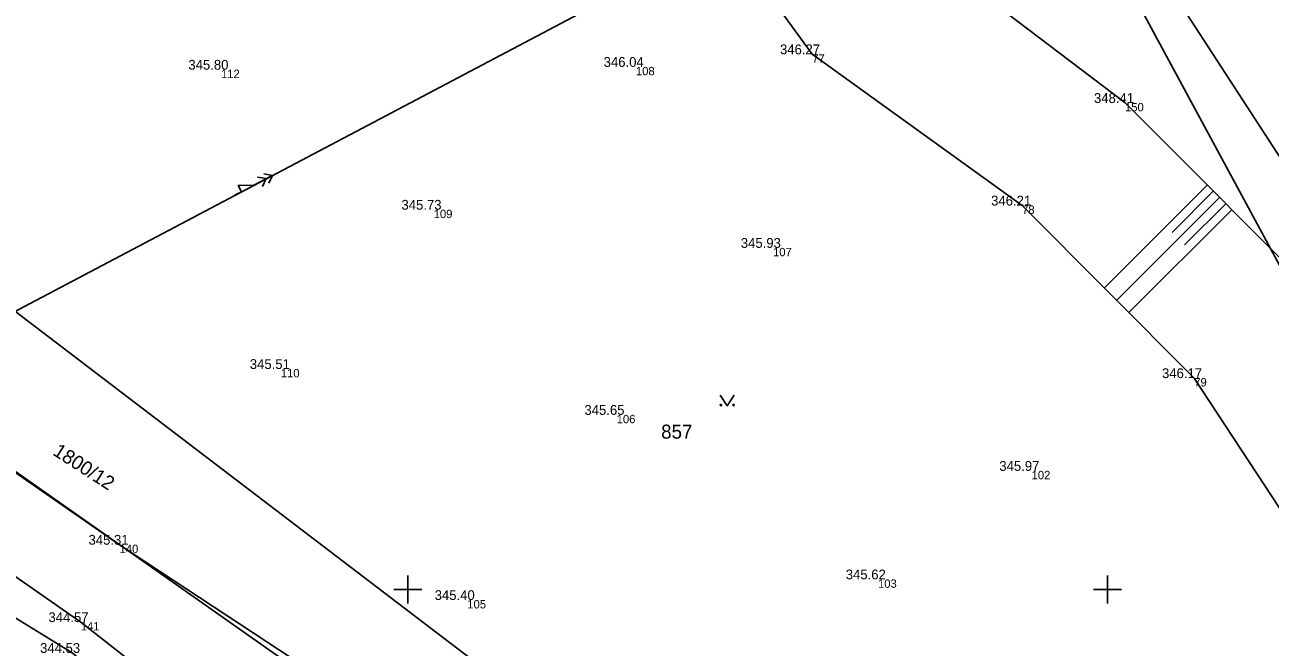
# Model space of a CAD drawing. Extents: x -614046 to -613877, y -1156755 to -1156623.
# Drawn here: x -613970.95 to -613935.35, y -1156701.64 to -1156683.87 of the extents above; entities that cross this region are included whole.
import ezdxf

# ---------------------------------------------------------------- set-up
doc = ezdxf.new("R2010")
doc.units = 0
for name, color, linetype in [('1-bod', 7, 'Continuous'), ('10-silnice', 7, 'Continuous'), ('14-terénní hrany', 7, 'Continuous'), ('15-šrafy', 7, 'Continuous'), ('16-vodní tok', 7, 'Continuous'), ('2-bod výška', 7, 'Continuous'), ('3-bod číslo', 7, 'Continuous'), ('32-elekrické vedení', 7, 'Continuous'), ('36-Značky kultur', 7, 'Continuous'), ('50-hranice parcel KN', 7, 'Continuous'), ('61-hektarová síť', 7, 'Continuous')]:
    doc.layers.add(name, color=color, linetype=linetype)

# ---------------------------------------------------------------- blocks, each defined once
blk = doc.blocks.new('6.61_1')
at = {"layer": '32-elekrické vedení'}
for points in [[(-3, 0), (-2.5, 0), (-2.5, 0.5), (-1.5, 0), (0, 0)], [(-1, 0.375), (-0.5, 0), (-1, -0.375)], [(-0.5, 0.375), (0, 0), (-0.5, -0.375)]]:
    blk.add_lwpolyline(points, dxfattribs=at)
blk = doc.blocks.new('3.14')
at = {"layer": '36-Značky kultur'}
blk.add_lwpolyline([(-0.5, 0.75), (0, 0), (0.5, 0.75)], dxfattribs=at)
for centre in [(-0.45, 0.05), (0.449, 0.05)]:
    blk.add_circle(centre, 0.05, dxfattribs=at)
blk = doc.blocks.new('POINT_DISPLAY')
blk.add_line((0, 0), (0, 0))

msp = doc.modelspace()

# ---------------------------------------------------------------- linework, layer by layer
at = {"layer": '10-silnice'}
msp.add_lwpolyline([(-613937.12, -1156718.51), (-613933.57, -1156717.58), (-613925.62, -1156715.79), (-613924.84, -1156714.33), (-613924.32, -1156712.22), (-613924.87, -1156710.22), (-613924.77, -1156707.77), (-613925.4, -1156704.88), (-613927.05, -1156701.37), (-613930.42, -1156695.41), (-613933.78, -1156689.64), (-613939.48, -1156680.87), (-613941.35, -1156679.26), (-613943.8, -1156674.41), (-613943.3, -1156673.71), (-613943.36, -1156673.41), (-613946.37, -1156666.81), (-613948.28, -1156662.1), (-613952.52, -1156653.05)], dxfattribs=at)
at = {"layer": '14-terénní hrany'}
for points in [[(-613997.04, -1156660.09), (-613993.56, -1156668.05), (-613988.66, -1156677.73), (-613984.98, -1156684.14), (-613979.93, -1156688.52), (-613976.6, -1156692.93), (-613968.24, -1156698.72), (-613963.28, -1156701.99), (-613959.08, -1156705.39), (-613955.46, -1156707.77), (-613951.07, -1156711.08), (-613944.86, -1156716.28)], [(-613940.16, -1156716.75), (-613937.91, -1156714.4), (-613933.94, -1156711.13), (-613930, -1156706.58), (-613928.58, -1156705.01), (-613927.95, -1156702.75), (-613928.18, -1156700.53), (-613933.55, -1156692.05), (-613939.5, -1156686.1), (-613943.86, -1156682.78), (-613948.89, -1156677.3), (-613953.73, -1156674.72)], [(-613951.83, -1156677.12), (-613952.88, -1156678.6), (-613948.44, -1156684.71), (-613942.44, -1156689.03), (-613937.52, -1156693.96), (-613931.49, -1156703.13), (-613933.8, -1156705.42), (-613937.38, -1156709.49), (-613940.48, -1156713.13)]]:
    msp.add_lwpolyline(points, dxfattribs=at)
at = {"layer": '15-šrafy'}
for p, q in [((-613937.15, -1156688.45), (-613940.09, -1156691.38)), ((-613936.98, -1156688.62), (-613938.15, -1156689.8)), ((-613936.8, -1156688.8), (-613939.74, -1156691.74)), ((-613936.45, -1156689.15), (-613939.39, -1156692.09)), ((-613936.62, -1156688.98), (-613937.8, -1156690.15))]:
    msp.add_line(p, q, dxfattribs=at)
at = {"layer": '16-vodní tok'}
for points in [[(-614001.52, -1156651.1), (-613998.11, -1156660.56), (-613996.01, -1156668.21), (-613990.4, -1156679.18), (-613986.72, -1156685.51), (-613977.75, -1156695.09), (-613969.35, -1156700.93), (-613963.95, -1156705.16), (-613955.95, -1156708.89), (-613951.7, -1156712.2), (-613945.56, -1156718.87), (-613945.478, -1156720.252)], [(-613947.4, -1156720.89), (-613951.41, -1156714.98), (-613956.19, -1156710.22), (-613963.8, -1156706.47), (-613969.59, -1156701.81), (-613978.15, -1156696.55), (-613986.41, -1156688.9), (-613987.27, -1156689.02), (-613988.53, -1156686.84), (-613992.1, -1156680.8), (-613997.89, -1156668.2), (-613999.34, -1156662.5), (-614003.52, -1156652.97)]]:
    msp.add_lwpolyline(points, dxfattribs=at)
at = {"layer": '32-elekrické vedení'}
msp.add_lwpolyline([(-614000.64, -1156707.56), (-613951.83, -1156681.82)], dxfattribs=at)
at = {"layer": '50-hranice parcel KN'}
for points in [[(-613939.01, -1156683.48), (-613927.48, -1156704.79)], [(-613943.81, -1156712.94), (-613974.5, -1156689.56)], [(-613947.86, -1156713.04), (-613979.96, -1156690.49)]]:
    msp.add_lwpolyline(points, dxfattribs=at)
at = {"layer": '61-hektarová síť'}
for points in [[(-613960, -1156700.4), (-613960, -1156700), (-613960, -1156699.6)], [(-613940, -1156700.4), (-613940, -1156700), (-613940, -1156699.6)], [(-613960.4, -1156700), (-613960, -1156700), (-613959.6, -1156700)], [(-613940.4, -1156700), (-613940, -1156700), (-613939.6, -1156700)]]:
    msp.add_lwpolyline(points, dxfattribs=at)

# ---------------------------------------------------------------- block references
at = {"layer": '1-bod'}
for p in [(-613948.44, -1156684.71), (-613965.34, -1156685.15), (-613953.48, -1156685.07), (-613939.5, -1156686.1), (-613959.26, -1156689.15), (-613942.44, -1156689.03), (-613949.56, -1156690.24), (-613963.63, -1156693.7), (-613937.52, -1156693.96), (-613954.03, -1156695.01), (-613942.17, -1156696.61), (-613968.24, -1156698.72), (-613946.56, -1156699.71), (-613958.3, -1156700.3), (-613969.35, -1156700.93)]:
    msp.add_blockref('POINT_DISPLAY', p, dxfattribs=at)
at = {"layer": '32-elekrické vedení', "xscale": 0.4, "yscale": 0.39999999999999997, "rotation": 27.804965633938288}
msp.add_blockref('6.61_1', (-613963.87, -1156688.169), dxfattribs=at)
at = {"layer": '36-Značky kultur', "xscale": 0.4, "yscale": 0.4000000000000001}
msp.add_blockref('3.14', (-613950.87, -1156694.75), dxfattribs=at)

# ---------------------------------------------------------------- texts
at = {"layer": '2-bod výška'}
for s, p in [('346.27 ', (-613949.362, -1156684.71)), ('345.80 ', (-613966.273, -1156685.15)), ('346.04 ', (-613954.402, -1156685.07)), ('348.41 ', (-613940.387, -1156686.1)), ('346.21 ', (-613943.327, -1156689.03)), ('345.73 ', (-613960.182, -1156689.15)), ('345.93 ', (-613950.482, -1156690.24)), ('345.51 ', (-613964.517, -1156693.7)), ('346.17 ', (-613938.442, -1156693.96)), ('345.65 ', (-613954.952, -1156695.01)), ('345.97 ', (-613943.092, -1156696.61)), ('345.31 ', (-613969.127, -1156698.72)), ('345.62 ', (-613947.482, -1156699.71)), ('345.40 ', (-613959.233, -1156700.3)), ('344.57 ', (-613970.272, -1156700.93)), ('344.53 ', (-613970.512, -1156701.81))]:
    msp.add_text(s, height=0.28, dxfattribs=at).set_placement(p)
at = {"layer": '3-bod číslo'}
for s, p in [('77', (-613948.44, -1156684.95)), ('112', (-613965.34, -1156685.39)), ('108', (-613953.48, -1156685.31)), ('150', (-613939.5, -1156686.34)), ('109', (-613959.26, -1156689.39)), ('78', (-613942.44, -1156689.27)), ('107', (-613949.56, -1156690.48)), ('110', (-613963.63, -1156693.94)), ('79', (-613937.52, -1156694.2)), ('106', (-613954.03, -1156695.25)), ('102', (-613942.17, -1156696.85)), ('140', (-613968.24, -1156698.96)), ('103', (-613946.56, -1156699.95)), ('105', (-613958.3, -1156700.54)), ('141', (-613969.35, -1156701.17))]:
    msp.add_text(s, height=0.24, dxfattribs=at).set_placement(p)
at = {"layer": '50-hranice parcel KN'}
msp.add_text('857', height=0.4, dxfattribs=at).set_placement((-613952.758, -1156695.69))
msp.add_text('1800/12', height=0.4, rotation=327.1983, dxfattribs=at).set_placement((-613970.174, -1156696.136))

doc.saveas('drawing.dxf')
